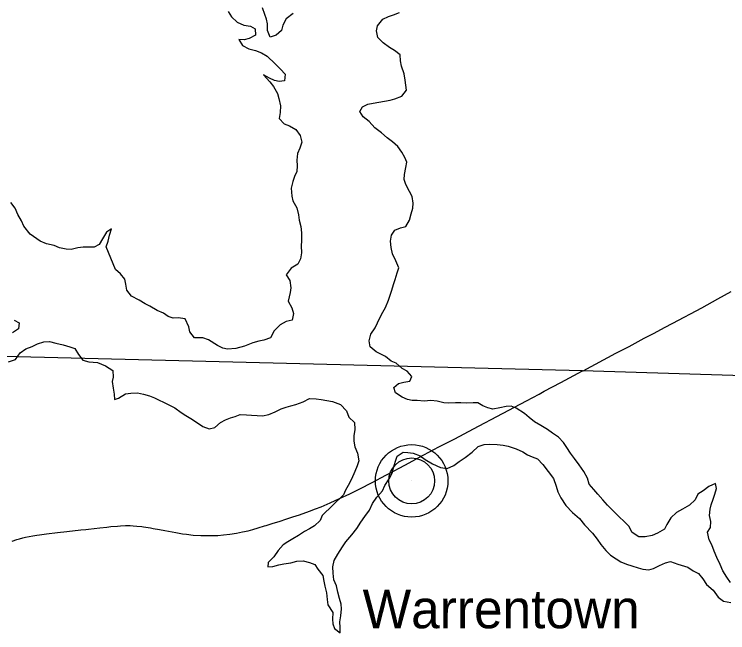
# Model space of a CAD drawing. Extents: x -29.6 to 34, y 0 to 22.
# Drawn here: x -20.252 to -18.877, y 5.661 to 6.851 of the extents above; entities that cross this region are included whole.
import ezdxf

# ---------------------------------------------------------------- set-up
doc = ezdxf.new("R2010")
doc.units = 0
for name, color, linetype in [('GM_X_Major_Lake', 7, 'Continuous'), ('GM_X_Township', 7, 'Continuous'), ('GM_X_Unincorporated', 7, 'Continuous'), ('GM_X_Unincorporated_Location', 7, 'Continuous'), ('GM_X_Unincorporated_Text', 7, 'Continuous'), ('GM_X_US_Route', 7, 'Continuous')]:
    doc.layers.add(name, color=color, linetype=linetype)

msp = doc.modelspace()

# ---------------------------------------------------------------- linework, layer by layer
at = {"layer": 'GM_X_Major_Lake'}
for points in [[(-19.7147, 6.8525), (-19.7278, 6.8425), (-19.7344, 6.83), (-19.7372, 6.8197), (-19.7471, 6.811), (-19.7587, 6.807), (-19.7638, 6.8198), (-19.7639, 6.8326), (-19.7662, 6.8418), (-19.7694, 6.851), (-19.7735, 6.8638)], [(-19.8398, 6.8565), (-19.8333, 6.8462), (-19.8226, 6.836), (-19.8094, 6.8301), (-19.7969, 6.828), (-19.7877, 6.8231), (-19.7872, 6.8111), (-19.7992, 6.8046), (-19.8088, 6.8023), (-19.8191, 6.8026), (-19.8122, 6.7913), (-19.8001, 6.785), (-19.7869, 6.7812), (-19.7755, 6.777), (-19.7644, 6.7704), (-19.749, 6.7556), (-19.739, 6.7457), (-19.73, 6.7362), (-19.7313, 6.723), (-19.7413, 6.7215), (-19.7505, 6.7236), (-19.7602, 6.7281), (-19.7716, 6.7348)], [(-19.5075, 6.4401), (-19.4976, 6.4424), (-19.4906, 6.4549), (-19.4871, 6.467), (-19.484, 6.4777), (-19.4834, 6.4873), (-19.4853, 6.5004), (-19.4904, 6.5103), (-19.4976, 6.5238), (-19.5009, 6.5333), (-19.5002, 6.5426), (-19.4975, 6.5565), (-19.4958, 6.5664), (-19.4995, 6.5757), (-19.5053, 6.5856), (-19.5128, 6.5965), (-19.5232, 6.6057), (-19.5336, 6.6134), (-19.5443, 6.6229), (-19.5575, 6.6328), (-19.5679, 6.6448), (-19.5797, 6.6535), (-19.5859, 6.6642), (-19.5813, 6.6731), (-19.5704, 6.6782), (-19.5605, 6.6804), (-19.5498, 6.6822), (-19.5388, 6.6841), (-19.5278, 6.6856), (-19.5186, 6.6885), (-19.5052, 6.6933), (-19.496, 6.7054), (-19.4972, 6.715), (-19.4987, 6.7246), (-19.5006, 6.7367), (-19.5057, 6.7512), (-19.5079, 6.7615), (-19.5087, 6.7732), (-19.5191, 6.7817), (-19.5287, 6.7873), (-19.5409, 6.7961), (-19.5513, 6.8063), (-19.5542, 6.8194), (-19.5522, 6.829), (-19.5417, 6.8416), (-19.531, 6.847), (-19.5215, 6.8499), (-19.5098, 6.8546)], [(-19.7716, 6.7348), (-19.7594, 6.7214), (-19.7522, 6.7122), (-19.7446, 6.6987), (-19.7421, 6.6892), (-19.7391, 6.675), (-19.7397, 6.6622), (-19.7417, 6.6504), (-19.732, 6.6402), (-19.7213, 6.6367), (-19.7092, 6.6294), (-19.7009, 6.618), (-19.6976, 6.6053), (-19.7014, 6.5932), (-19.7063, 6.5835), (-19.7072, 6.5704), (-19.7071, 6.5593), (-19.7077, 6.5483), (-19.7123, 6.539), (-19.715, 6.5294), (-19.7181, 6.5162), (-19.7169, 6.5013), (-19.715, 6.4921), (-19.7078, 6.4783), (-19.7041, 6.4651), (-19.7033, 6.4548), (-19.7, 6.4428), (-19.6985, 6.4307), (-19.6984, 6.4151), (-19.699, 6.4055), (-19.6985, 6.392), (-19.7005, 6.3802), (-19.7054, 6.3702), (-19.7181, 6.3623), (-19.7283, 6.3497), (-19.7208, 6.3384), (-19.7192, 6.3249), (-19.7202, 6.3153), (-19.7243, 6.2989), (-19.7171, 6.2858), (-19.7138, 6.2752), (-19.7165, 6.2624), (-19.7282, 6.2601), (-19.7399, 6.2536), (-19.7511, 6.2418), (-19.7581, 6.2286), (-19.7709, 6.2239), (-19.7804, 6.2217), (-19.7921, 6.2184), (-19.8084, 6.2122), (-19.8251, 6.2078), (-19.841, 6.2062), (-19.8503, 6.2086), (-19.8606, 6.2135), (-19.8774, 6.2248), (-19.8885, 6.2286), (-19.9048, 6.2281), (-19.9134, 6.2397), (-19.9157, 6.2493), (-19.9226, 6.2649), (-19.9364, 6.2669), (-19.9457, 6.2661), (-19.9553, 6.2693), (-19.9646, 6.2759), (-19.9763, 6.2812), (-19.9906, 6.2892), (-19.9995, 6.2941), (-20.0113, 6.3011), (-20.0263, 6.3088), (-20.0353, 6.3201), (-20.0372, 6.3319), (-20.0387, 6.3411), (-20.047, 6.3517), (-20.0566, 6.3598)], [(-20.0566, 6.3598), (-20.0747, 6.4034), (-20.0709, 6.4144), (-20.0682, 6.4262), (-20.0643, 6.4379), (-20.0739, 6.4318), (-20.0819, 6.419), (-20.0886, 6.4083), (-20.0981, 6.4029), (-20.1077, 6.4031), (-20.119, 6.4027), (-20.1296, 6.4019), (-20.1424, 6.3986), (-20.1519, 6.3993), (-20.1644, 6.4017), (-20.1747, 6.4059), (-20.1899, 6.4093), (-20.202, 6.4142), (-20.2209, 6.4276), (-20.2337, 6.4431), (-20.2381, 6.4537), (-20.2452, 6.4658), (-20.2503, 6.4778), (-20.2585, 6.4891)], [(-18.9127, 5.8865), (-18.911, 5.8982), (-18.9093, 5.9071), (-18.9055, 5.9175), (-18.9021, 5.9271), (-18.899, 5.9385), (-18.9012, 5.9477), (-18.9139, 5.9419), (-18.9249, 5.934), (-18.9351, 5.9275), (-18.94, 5.9165), (-18.9509, 5.9061), (-18.9647, 5.8988), (-18.976, 5.8923), (-18.9869, 5.8819), (-18.9946, 5.8691), (-18.9991, 5.8601), (-19.0129, 5.8522), (-19.0232, 5.8478), (-19.0366, 5.8452), (-19.0484, 5.8451), (-19.0612, 5.8536), (-19.0681, 5.8656), (-19.0767, 5.8748), (-19.0867, 5.8836), (-19.0996, 5.8966), (-19.109, 5.9065), (-19.1179, 5.9164), (-19.1276, 5.9273), (-19.1355, 5.9365), (-19.1445, 5.9464), (-19.1475, 5.9581), (-19.1543, 5.9709), (-19.1637, 5.9839), (-19.1727, 5.996), (-19.1802, 6.0062), (-19.1871, 6.0172), (-19.1939, 6.0267), (-19.2036, 6.037), (-19.2151, 6.045), (-19.2244, 6.0517), (-19.2376, 6.0594), (-19.2497, 6.0664), (-19.2601, 6.0752), (-19.269, 6.0826), (-19.2851, 6.0932), (-19.2944, 6.097), (-19.3043, 6.0959), (-19.3167, 6.0936), (-19.3302, 6.091), (-19.3398, 6.0938), (-19.3491, 6.0976), (-19.3587, 6.1032), (-19.3676, 6.1032), (-19.3808, 6.1023), (-19.3914, 6.103), (-19.4017, 6.1029), (-19.4152, 6.1024), (-19.4241, 6.103), (-19.4369, 6.1061), (-19.4494, 6.1078), (-19.4625, 6.1066), (-19.4757, 6.1076), (-19.4856, 6.1075), (-19.4945, 6.1099), (-19.5048, 6.1144), (-19.5174, 6.1225), (-19.5206, 6.1328), (-19.5115, 6.1407), (-19.5012, 6.1429), (-19.4899, 6.1452), (-19.486, 6.1541), (-19.495, 6.1643), (-19.5043, 6.1696), (-19.5161, 6.1794), (-19.5257, 6.1833), (-19.5365, 6.1921), (-19.5454, 6.1966), (-19.5547, 6.2015), (-19.5665, 6.211), (-19.5684, 6.2224), (-19.5649, 6.2356), (-19.5565, 6.2477), (-19.5523, 6.2574), (-19.5468, 6.2681), (-19.5419, 6.2777), (-19.5366, 6.2866), (-19.5311, 6.3009), (-19.528, 6.3105), (-19.5242, 6.3202), (-19.5211, 6.3312), (-19.5183, 6.3405), (-19.5142, 6.3533), (-19.511, 6.3633), (-19.5165, 6.3768), (-19.5234, 6.3899), (-19.526, 6.4023), (-19.5268, 6.4144), (-19.5248, 6.4258), (-19.5185, 6.4358), (-19.5075, 6.4401)], [(-20.252, 6.2624), (-20.2427, 6.2575), (-20.2437, 6.2458), (-20.2553, 6.2379)], [(-20.2627, 6.182), (-20.2497, 6.1867), (-20.2402, 6.1993), (-20.2296, 6.2071), (-20.2176, 6.2119), (-20.207, 6.2165), (-20.195, 6.2205), (-20.184, 6.221), (-20.1719, 6.2182), (-20.1577, 6.2151), (-20.145, 6.2113), (-20.1354, 6.2075), (-20.1278, 6.1965), (-20.12, 6.1852), (-20.1079, 6.1824), (-20.0912, 6.1808), (-20.076, 6.1745), (-20.0617, 6.1657), (-20.0616, 6.1529), (-20.063, 6.144), (-20.0615, 6.1316), (-20.0593, 6.1202), (-20.0585, 6.1095), (-20.0508, 6.1123)], [(-20.0508, 6.1123), (-20.0377, 6.1206), (-20.0271, 6.1218), (-20.0147, 6.1222), (-20.0026, 6.1202), (-19.9915, 6.1164), (-19.9815, 6.1129), (-19.9551, 6.1), (-19.9426, 6.0937), (-19.9305, 6.0849), (-19.9215, 6.0789), (-19.9119, 6.073), (-19.8972, 6.0635), (-19.8883, 6.0575), (-19.8762, 6.053), (-19.8652, 6.0556), (-19.8543, 6.0656), (-19.8451, 6.0703), (-19.8355, 6.0743), (-19.826, 6.0769), (-19.8168, 6.0809), (-19.8043, 6.0803), (-19.7951, 6.0793), (-19.7837, 6.0787), (-19.7734, 6.078), (-19.7614, 6.081), (-19.7493, 6.0861), (-19.7377, 6.0919), (-19.7281, 6.0951), (-19.7189, 6.0977), (-19.7093, 6.1003), (-19.6955, 6.1054), (-19.6828, 6.1115), (-19.67, 6.1109), (-19.6607, 6.1099), (-19.6494, 6.1079), (-19.6387, 6.1059), (-19.6234, 6.1003), (-19.6119, 6.0876), (-19.6071, 6.0759), (-19.5967, 6.0653), (-19.5956, 6.0518), (-19.5976, 6.0397), (-19.5975, 6.0297), (-19.596, 6.0187), (-19.5909, 6.0063), (-19.5879, 5.9914), (-19.591, 5.9818), (-19.5955, 5.9707), (-19.6021, 5.9564), (-19.6088, 5.9443), (-19.614, 5.935), (-19.6178, 5.9261), (-19.659, 5.8862), (-19.6625, 5.877), (-19.6737, 5.8666), (-19.6829, 5.8604), (-19.6928, 5.8554), (-19.7045, 5.8478), (-19.7154, 5.8417), (-19.725, 5.8359), (-19.7341, 5.8301), (-19.7433, 5.8187), (-19.752, 5.8068), (-19.7626, 5.7961), (-19.7636, 5.7872), (-19.754, 5.7883), (-19.742, 5.7916), (-19.7327, 5.7931), (-19.7193, 5.7954), (-19.7076, 5.7983), (-19.6955, 5.7988), (-19.683, 5.796), (-19.6727, 5.7922), (-19.6669, 5.7827), (-19.6576, 5.771), (-19.6557, 5.76), (-19.6535, 5.7504), (-19.6505, 5.7373), (-19.6493, 5.7245), (-19.6478, 5.7142), (-19.6381, 5.6993), (-19.639, 5.6869), (-19.6382, 5.678), (-19.6349, 5.6687), (-19.6242, 5.6607), (-19.6243, 5.6706), (-19.6248, 5.6816), (-19.6227, 5.6934), (-19.6214, 5.7069), (-19.6222, 5.7158), (-19.6252, 5.7268), (-19.6285, 5.7389), (-19.6311, 5.751), (-19.6362, 5.7626), (-19.6377, 5.7754), (-19.6382, 5.7875), (-19.6358, 5.8), (-19.6288, 5.8122), (-19.6194, 5.8261), (-19.6131, 5.8358)], [(-19.6131, 5.8358), (-19.6015, 5.849), (-19.5916, 5.8612), (-19.5839, 5.8734), (-19.5762, 5.8841), (-19.5678, 5.8963), (-19.5619, 5.9095), (-19.5535, 5.9213), (-19.5426, 5.9335), (-19.5377, 5.9442), (-19.5293, 5.9567), (-19.5234, 5.9688), (-19.5213, 5.9781), (-19.5172, 5.9906), (-19.5144, 6.0006), (-19.5028, 6.0085), (-19.4939, 6.0078), (-19.4836, 6.0062), (-19.4697, 6.0009), (-19.46, 5.9939), (-19.4461, 5.9858), (-19.4304, 5.9789), (-19.4176, 5.9768), (-19.4052, 5.9823), (-19.395, 5.9902), (-19.383, 5.9981), (-19.3699, 6.0085), (-19.3583, 6.0193), (-19.3463, 6.023), (-19.3367, 6.0234), (-19.3218, 6.0232), (-19.3097, 6.0215), (-19.3004, 6.0198), (-19.2851, 6.0146), (-19.2723, 6.0086), (-19.2633, 6.0034), (-19.2544, 5.9995), (-19.2441, 5.9954), (-19.2333, 5.9844), (-19.2236, 5.971), (-19.2132, 5.9576), (-19.2081, 5.9427), (-19.2048, 5.932), (-19.1986, 5.9203), (-19.1892, 5.9058), (-19.1763, 5.8921), (-19.1631, 5.8805), (-19.153, 5.8684), (-19.1379, 5.8526), (-19.1286, 5.8406), (-19.1221, 5.8306), (-19.1124, 5.819), (-19.1031, 5.8102), (-19.092, 5.8028), (-19.0831, 5.7972), (-19.0724, 5.7927), (-19.0624, 5.7892), (-19.0496, 5.7857), (-19.0407, 5.783), (-19.0293, 5.782), (-19.0201, 5.7842), (-19.0088, 5.79), (-18.9971, 5.7951), (-18.9879, 5.798), (-18.9736, 5.7928), (-18.954, 5.7869), (-18.944, 5.7795), (-18.934, 5.7746), (-18.9254, 5.7647), (-18.9182, 5.7538), (-18.9057, 5.7428), (-18.8956, 5.7291), (-18.8856, 5.7213), (-18.8717, 5.7186)], [(-18.8721, 5.7573), (-18.8789, 5.7676), (-18.8865, 5.78), (-18.8919, 5.792), (-18.8981, 5.8055), (-18.9035, 5.8175), (-18.9083, 5.8296), (-18.9133, 5.8392), (-18.9163, 5.8541), (-18.9107, 5.863), (-18.9097, 5.8748), (-18.9127, 5.8865)]]:
    msp.add_lwpolyline(points, dxfattribs=at)
at = {"layer": 'GM_X_Township'}
msp.add_lwpolyline([(-17.8742, 6.1253), (-19.1572, 6.1651), (-20.7391, 6.2042), (-21.4075, 6.2188), (-21.6713, 6.2244), (-21.6682, 6.402), (-21.6504, 7.1784), (-21.6499, 7.2446), (-21.6214, 8.5068), (-21.5392, 10.9421), (-21.5395, 10.9431), (-21.5399, 10.9443), (-21.5403, 10.9462), (-21.5405, 10.9479), (-21.5406, 10.9493), (-21.5407, 10.956), (-21.5408, 10.9609), (-21.5413, 10.9689), (-21.5414, 10.9701), (-19.4178, 10.9099), (-18.9861, 10.8993), (-17.4554, 10.8405)], dxfattribs=at)
at = {"layer": 'GM_X_Unincorporated'}
for radius in [0.0698, 0.0442]:
    msp.add_circle((-19.4862, 5.9529), radius, dxfattribs=at)
at = {"layer": 'GM_X_Unincorporated_Location'}
msp.add_line((-19.4862, 5.9529), (-19.4862, 5.9529), dxfattribs=at)
at = {"layer": 'GM_X_US_Route'}
for points in [[(-19.1561, 6.165), (-19.0927, 6.1987), (-19.0824, 6.2041), (-19.0674, 6.2119), (-19.0382, 6.2276), (-19.0191, 6.2376), (-18.999, 6.2482), (-18.9831, 6.2566), (-18.9275, 6.286), (-18.8963, 6.3031), (-18.8709, 6.3173)], [(-19.7666, 5.8672), (-19.7553, 5.8706), (-19.7398, 5.8755), (-19.7285, 5.8792), (-19.7151, 5.8835), (-19.7025, 5.8879), (-19.6832, 5.8948), (-19.6714, 5.8992), (-19.6609, 5.9033), (-19.6432, 5.911), (-19.6253, 5.9188), (-19.6057, 5.9281), (-19.604, 5.9289), (-19.5864, 5.9377), (-19.5625, 5.95), (-19.5362, 5.9639), (-19.5311, 5.9666), (-19.4997, 5.9832), (-19.4629, 6.0028), (-19.4339, 6.0182), (-19.4034, 6.0342), (-19.3674, 6.0532), (-19.3561, 6.0592), (-19.3221, 6.0772), (-19.265, 6.1073), (-19.2408, 6.1202), (-19.2308, 6.1255), (-19.1986, 6.1425), (-19.157, 6.1646), (-19.1561, 6.165)], [(-20.2562, 5.8369), (-20.2466, 5.84), (-20.242, 5.8414), (-20.2351, 5.8431), (-20.23, 5.8443), (-20.2163, 5.847), (-20.2081, 5.8483), (-20.2034, 5.849), (-20.1895, 5.851), (-20.1688, 5.8534), (-20.1508, 5.8555), (-20.1237, 5.8585), (-20.1137, 5.8596), (-20.1086, 5.8602), (-20.0868, 5.8625), (-20.0735, 5.8641), (-20.0659, 5.8649), (-20.0532, 5.8661), (-20.0471, 5.8665), (-20.0376, 5.8669), (-20.0345, 5.8669), (-20.0283, 5.8668), (-20.0228, 5.8666), (-20.0158, 5.8661), (-20.0063, 5.8652), (-20.0027, 5.8647), (-19.9982, 5.8641), (-19.9896, 5.8626), (-19.9843, 5.8616), (-19.9722, 5.8594), (-19.9621, 5.8573), (-19.9406, 5.8535), (-19.9277, 5.8511), (-19.9199, 5.8501), (-19.9075, 5.8487), (-19.8926, 5.8478), (-19.8816, 5.8475), (-19.87, 5.8476), (-19.8595, 5.8481), (-19.8489, 5.8489), (-19.8368, 5.8504), (-19.8236, 5.8524), (-19.8121, 5.8546), (-19.8014, 5.8569), (-19.7925, 5.8593), (-19.7817, 5.8624), (-19.7695, 5.8663), (-19.7666, 5.8672)]]:
    msp.add_lwpolyline(points, dxfattribs=at)

# ---------------------------------------------------------------- texts
at = {"layer": 'GM_X_Unincorporated_Text'}
msp.add_text('Warrentown', height=0.07404, rotation=0, dxfattribs=at).set_placement((-19.5807, 5.6692))

doc.saveas('drawing.dxf')
